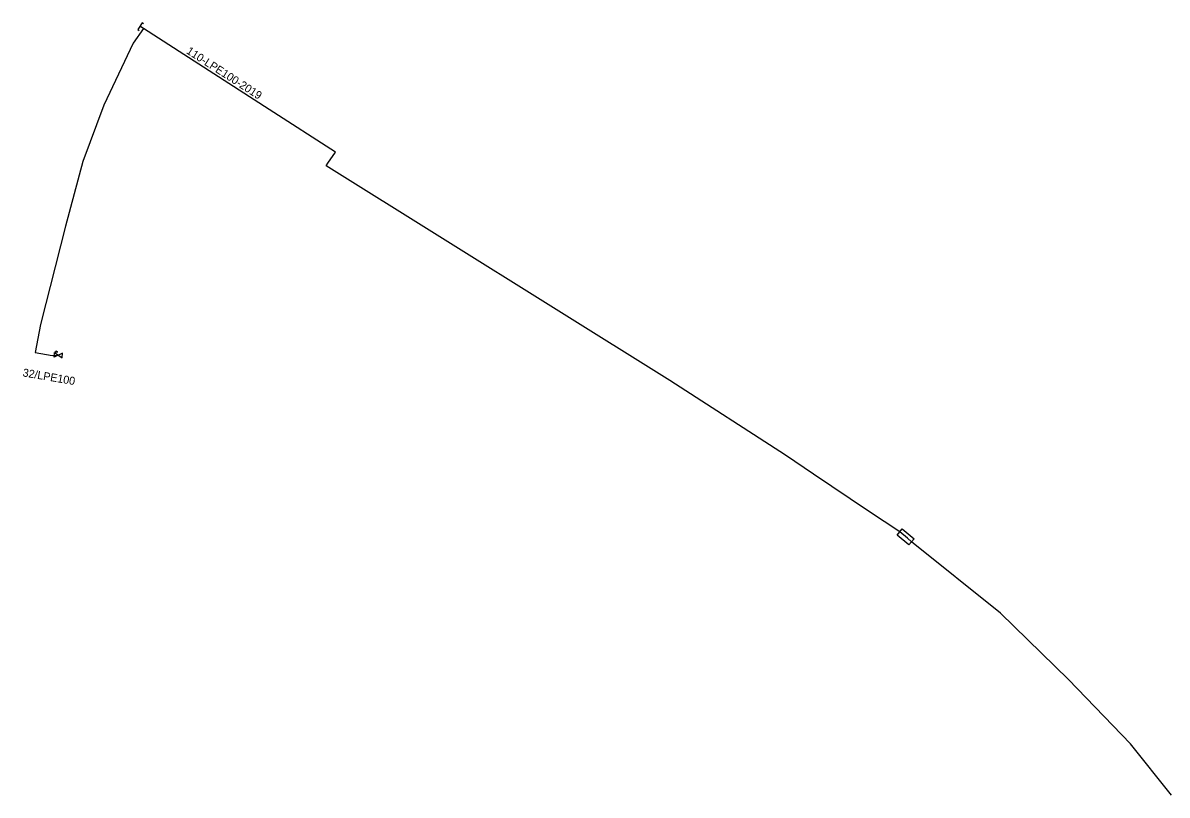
# Model space of a CAD drawing. Extents: x -787723 to -786204, y -1153846 to -1152384.
# Drawn here: x -787723 to -787579.9, y -1153775.3 to -1153678.9 of the extents above; entities that cross this region are included whole.
import ezdxf

# ---------------------------------------------------------------- set-up
doc = ezdxf.new("R2010")
doc.units = 0
for name, color, linetype in [('Vrstva 1', 7, 'Continuous'), ('Vrstva 21', 7, 'Continuous'), ('Vrstva 22', 7, 'Continuous'), ('Vrstva 29', 7, 'Continuous'), ('Vrstva 31', 7, 'Continuous'), ('Vrstva 32', 7, 'Continuous')]:
    doc.layers.add(name, color=color, linetype=linetype)

# ---------------------------------------------------------------- blocks, each defined once
blk = doc.blocks.new('DEC063-SN')
at = {"layer": 'Vrstva 1'}
for p, q in [((-0.5, -0.3), (0.5, 0.3)), ((0.5, -0.3), (-0.5, 0.3)), ((-0.5, 0.3), (-0.5, -0.3)), ((0.5, 0.3), (0.5, -0.3)), ((0.126, -0.318), (0.126, -0.458)), ((0.126, -0.384), (0.206, -0.384)), ((0.206, -0.458), (0.206, -0.318)), ((0.366, -0.458), (0.366, -0.318))]:
    blk.add_line(p, q, dxfattribs=at)
for points in [[(0.246, -0.318), (0.246, -0.418), (0.252, -0.438), (0.264, -0.451), (0.281, -0.458), (0.292, -0.458), (0.309, -0.451), (0.321, -0.438), (0.326, -0.418), (0.326, -0.318)], [(0.366, -0.318), (0.418, -0.318), (0.435, -0.325), (0.441, -0.331), (0.446, -0.344), (0.446, -0.364), (0.441, -0.378), (0.435, -0.384), (0.418, -0.391), (0.366, -0.391)]]:
    blk.add_lwpolyline(points, dxfattribs=at)
blk = doc.blocks.new('DEC130')
at = {"layer": 'Vrstva 1'}
blk.add_lwpolyline([(0.2, 0.5), (0, 0.5), (0, -0.5), (0.2, -0.5)], dxfattribs=at)

msp = doc.modelspace()

# ---------------------------------------------------------------- linework, layer by layer
at = {"layer": 'Vrstva 21'}
msp.add_lwpolyline([(-787579.39, -1153775.34), (-787584.52, -1153768.93), (-787592.27, -1153760.92), (-787600.76, -1153752.6), (-787611.9, -1153743.7), (-787612.41, -1153743.26), (-787613.37, -1153742.48), (-787617.25, -1153739.88), (-787624.13, -1153735.24), (-787627.63, -1153732.87), (-787642.12, -1153723.54), (-787685.06, -1153696.73), (-787684.84, -1153696.43), (-787683.88, -1153695.06), (-787692.18, -1153689.71), (-787707.9, -1153679.59), (-787708.32, -1153679.32)], dxfattribs=at)
at = {"layer": 'Vrstva 29'}
msp.add_lwpolyline([(-787612.22, -1153744.08), (-787613.69, -1153742.86), (-787613.05, -1153742.1), (-787611.58, -1153743.32)], close=True, dxfattribs=at)
at = {"layer": 'Vrstva 31'}
msp.add_lwpolyline([(-787707.9, -1153679.59), (-787709.17, -1153681.41), (-787712.82, -1153689.17), (-787715.46, -1153696.22), (-787717.64, -1153704.27), (-787719.53, -1153711.82), (-787720.1, -1153713.94), (-787720.74, -1153716.57), (-787721.41, -1153720.06), (-787719.3, -1153720.42), (-787718.53, -1153720.39)], dxfattribs=at)

# ---------------------------------------------------------------- block references
at = {"layer": 'Vrstva 22', "rotation": -32.66517501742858}
msp.add_blockref('DEC130', (-787708.32, -1153679.32), dxfattribs=at)
at = {"layer": 'Vrstva 32', "rotation": 174.8724743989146}
msp.add_blockref('DEC063-SN', (-787718.53, -1153720.39), dxfattribs=at)

# ---------------------------------------------------------------- texts
at = {"layer": 'Vrstva 21'}
msp.add_text('110-LPE100-2019', height=1, rotation=327.228, dxfattribs=at).set_placement((-787702.62, -1153682.64))
at = {"layer": 'Vrstva 31'}
msp.add_text('32/LPE100', height=1, rotation=350.318, dxfattribs=at).set_placement((-787723.04, -1153723.03))

doc.saveas('drawing.dxf')
